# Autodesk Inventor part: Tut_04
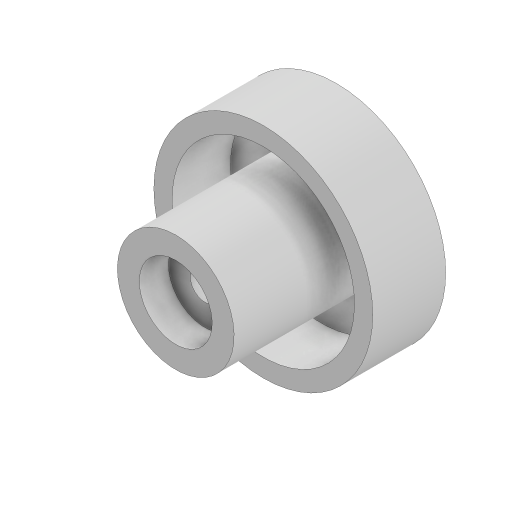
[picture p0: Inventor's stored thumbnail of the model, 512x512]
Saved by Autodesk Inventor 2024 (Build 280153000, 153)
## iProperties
Created: 2019-02
Part Number: Tut_04
Material: Generic
Document SubType Name: Modeling
Designer: LENOVO-CADCIM
Density: 1 g/cm^3
Appearance: Default
Author: LENOVO-CADCIM
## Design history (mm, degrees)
revolve "Revolution1" stored, may be unused: angle "d31" = 90 deg
body "Solid1"
sketch "Sketch1"
  geometry: L1 (0, 0)-(0, 22); L2 (0, 22)-(4, 22); L3 (4, 22)-(4, 36); L4 (4, 36)-(10, 36); L5 (10, 36)-(10, 44); L6 (10, 44)-(16, 44); L7 (16, 44)-(16, 4); L8 (16, 4)-(25, 4); L9 (25, 4)-(25, 20); L10 (25, 20)-(30, 20); L11 (30, 20)-(30, 0); L12 (30, 0)-(0, 0); 1 further point
  constraints: 24 end point, 11 perpendicular, 1 midpoint, 1 vertical
  dimensions: "d21" = 22 distance of L1.start L1.end; "d22" = 36 distance between parallel lines of L12 L4; "d23" = 44 distance between parallel lines of L12 L6; "d24" = 25 distance between parallel lines of L9 L1; "d25" = 30 distance from line of point (30, 10) L1; "d26" = 4 distance between parallel lines of L8 L12; "d27" = 4 distance between parallel lines of L1 L3; "d28" = 10 distance between parallel lines of L5 L1; "d29" = 16 distance between parallel lines of L7 L1; "d30" = 20 distance of L10.end L11.end
